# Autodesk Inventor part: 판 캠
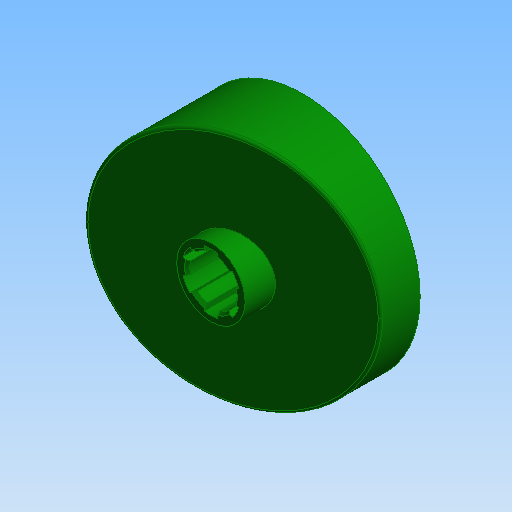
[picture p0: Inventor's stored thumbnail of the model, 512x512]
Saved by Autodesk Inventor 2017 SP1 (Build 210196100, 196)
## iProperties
Created: 2021-07
Part Number: 판 캠
Document SubType Name: 모델링
Designer: mdu
Material: 알루미늄 6061
Density: 2.71 g/cm^3
Mass: 235.299 g
Surface Area: 331.303 cm^2
Volume: 86.8264 cm^3
Appearance: 진녹색
변환 표준: STEP AP214IS
파일 이름: C:\Users\SeoGD\Desktop\?쒗뿕\??stp
전처리기: Build: 253, Release: 2010 SP1 - Date: Wed 07/29/2009
전송 단위: 밀리미터
불확실성: 0.01
Author: mdu
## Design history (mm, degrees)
node "작업 평면4"
sketch "스케치1"
  geometry: C1 r 44.5 at (0, 0); 1 further point
  constraints: 1 centre point, 1 coincident
  dimensions: "d25" = 89 diameter of C1
extrude "돌출1" new body sketch "스케치1" distance "d1" = 40; taper "d2" = 0 deg
sketch "스케치2"
  geometry: L1 (-44.5, 15)-(44.5, 38.847); L2 (-44.5, 0)-(-44.5, 40) reference; L3 (-44.5, 40)-(44.5, 40) reference; L4 (44.5, 0)-(44.5, 40) reference; 1 further point
  constraints: 2 end point, 2 point on line
  dimensions: "d26" = 15 distance of L2.start L1.start; "d27" = 75 deg angle of L1 L2
extrude "돌출2" cut sketch "스케치2" stored distance "d5" = 40; taper "d6" = 0 deg
node "작업 평면1"
sketch "스케치3"
  geometry: C1 r 13 at (0, 0); 1 further point
  constraints: 1 centre point, 1 coincident
  dimensions: "d9" = 26 diameter of C1
extrude "돌출3" join sketch "스케치3" distance "d10" = 38; taper "d11" = 0 deg
hole "구멍1" diameter "d14" = 18; stored, may be unused: countersink angle "d18" = 90 deg, drill point angle "d20" = 118 deg; dims "d12" = 10, "d13" = 10, "d15" = 6, "d16" = 4, "d17" = 2, "d19" = 8
feature "쉘2" dims "d29" = 5
sketch "스케치6"
  geometry: C1 r 17.5 at (0, 0); C2 r 14 at (0, 0) reference; 1 further point
  constraints: 1 centre point, 1 coincident
  dimensions: "d28" = 35 diameter of C1
extrude "돌출4" join sketch "스케치6" stored distance "d30" = 38; taper "d31" = 0 deg
fillet "모깎기1" dims "d32" = 3
chamfer "모따기1" distance "d21" = 1; stored, may be unused: second distance "d22" = 2, angle "d23" = 45 deg
sketch "스케치7"
  geometry: L1 (-12.374, 12.374)-(-27.931, 27.931); A1 r 39.5 centre (0, 0) between (-27.931, 27.931) and (0, 39.5) reference; 2 further points
  constraints: 2 end point, 2 point on circle, 1 point on line, 1 vertical alignment, 2 other
  dimensions: "d33" = 45 deg dimension on point (0, 0) L1.start A1.end
feature "리브1" sketch "스케치7" dims "d34" = 5, "d35" = 1, "d36" = 0
fillet "모깎기2" dims "d37" = 3
sketch "스케치8"
  geometry: L1 (2.5, 10.712)-(2.5, 8.646); L2 (-2.5, 10.712)-(-2.5, 8.646); A1 r 11 centre (0, 0) between (2.5, 10.712) and (-2.5, 10.712); A2 r 9 centre (0, 0) between (2.5, 8.646) and (-2.5, 8.646) reference; 1 further point
  constraints: 4 end point, 4 point on circle, 2 parallel, 1 centre point, 1 coincident, 1 vertical
  dimensions: "d41" = 22 diameter of A1; "d42" = 5 distance between parallel lines of L1 L2
extrude "돌출5" cut sketch "스케치8" stored distance "d43" = 38; taper "d44" = 0 deg
fillet "모깎기3" dims "d48" = 1
node "솔리드1"
node "솔리드 본체"
node "곡면 본체"
pattern_circular "원형 패턴1" dims angle "d39" = 360 deg
pattern_circular "원형 패턴2" dims angle "d46" = 360 deg
node "솔리드2"
